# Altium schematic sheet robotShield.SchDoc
size A2; DocumentNumber: 3; SheetNumber: 1; SheetTotal: 1; PageSetup: Record=PageOptions¦CenterHorizontal=True¦CenterVertical=True¦PrintScale=0.73¦XCorrection=1.00¦YCorrection=1.00¦PrintKind=0¦BorderSize=5000000¦LeftOffset=0¦BottomOffset=0¦Orientation=2¦PaperLength=1000¦PaperWidth=1000¦Scale=100¦PaperSource=7¦PrintQuality=-3¦MediaType=1¦DitherType=10¦PrintScaleMode=1¦PaperKind=A3¦PaperIndex=8
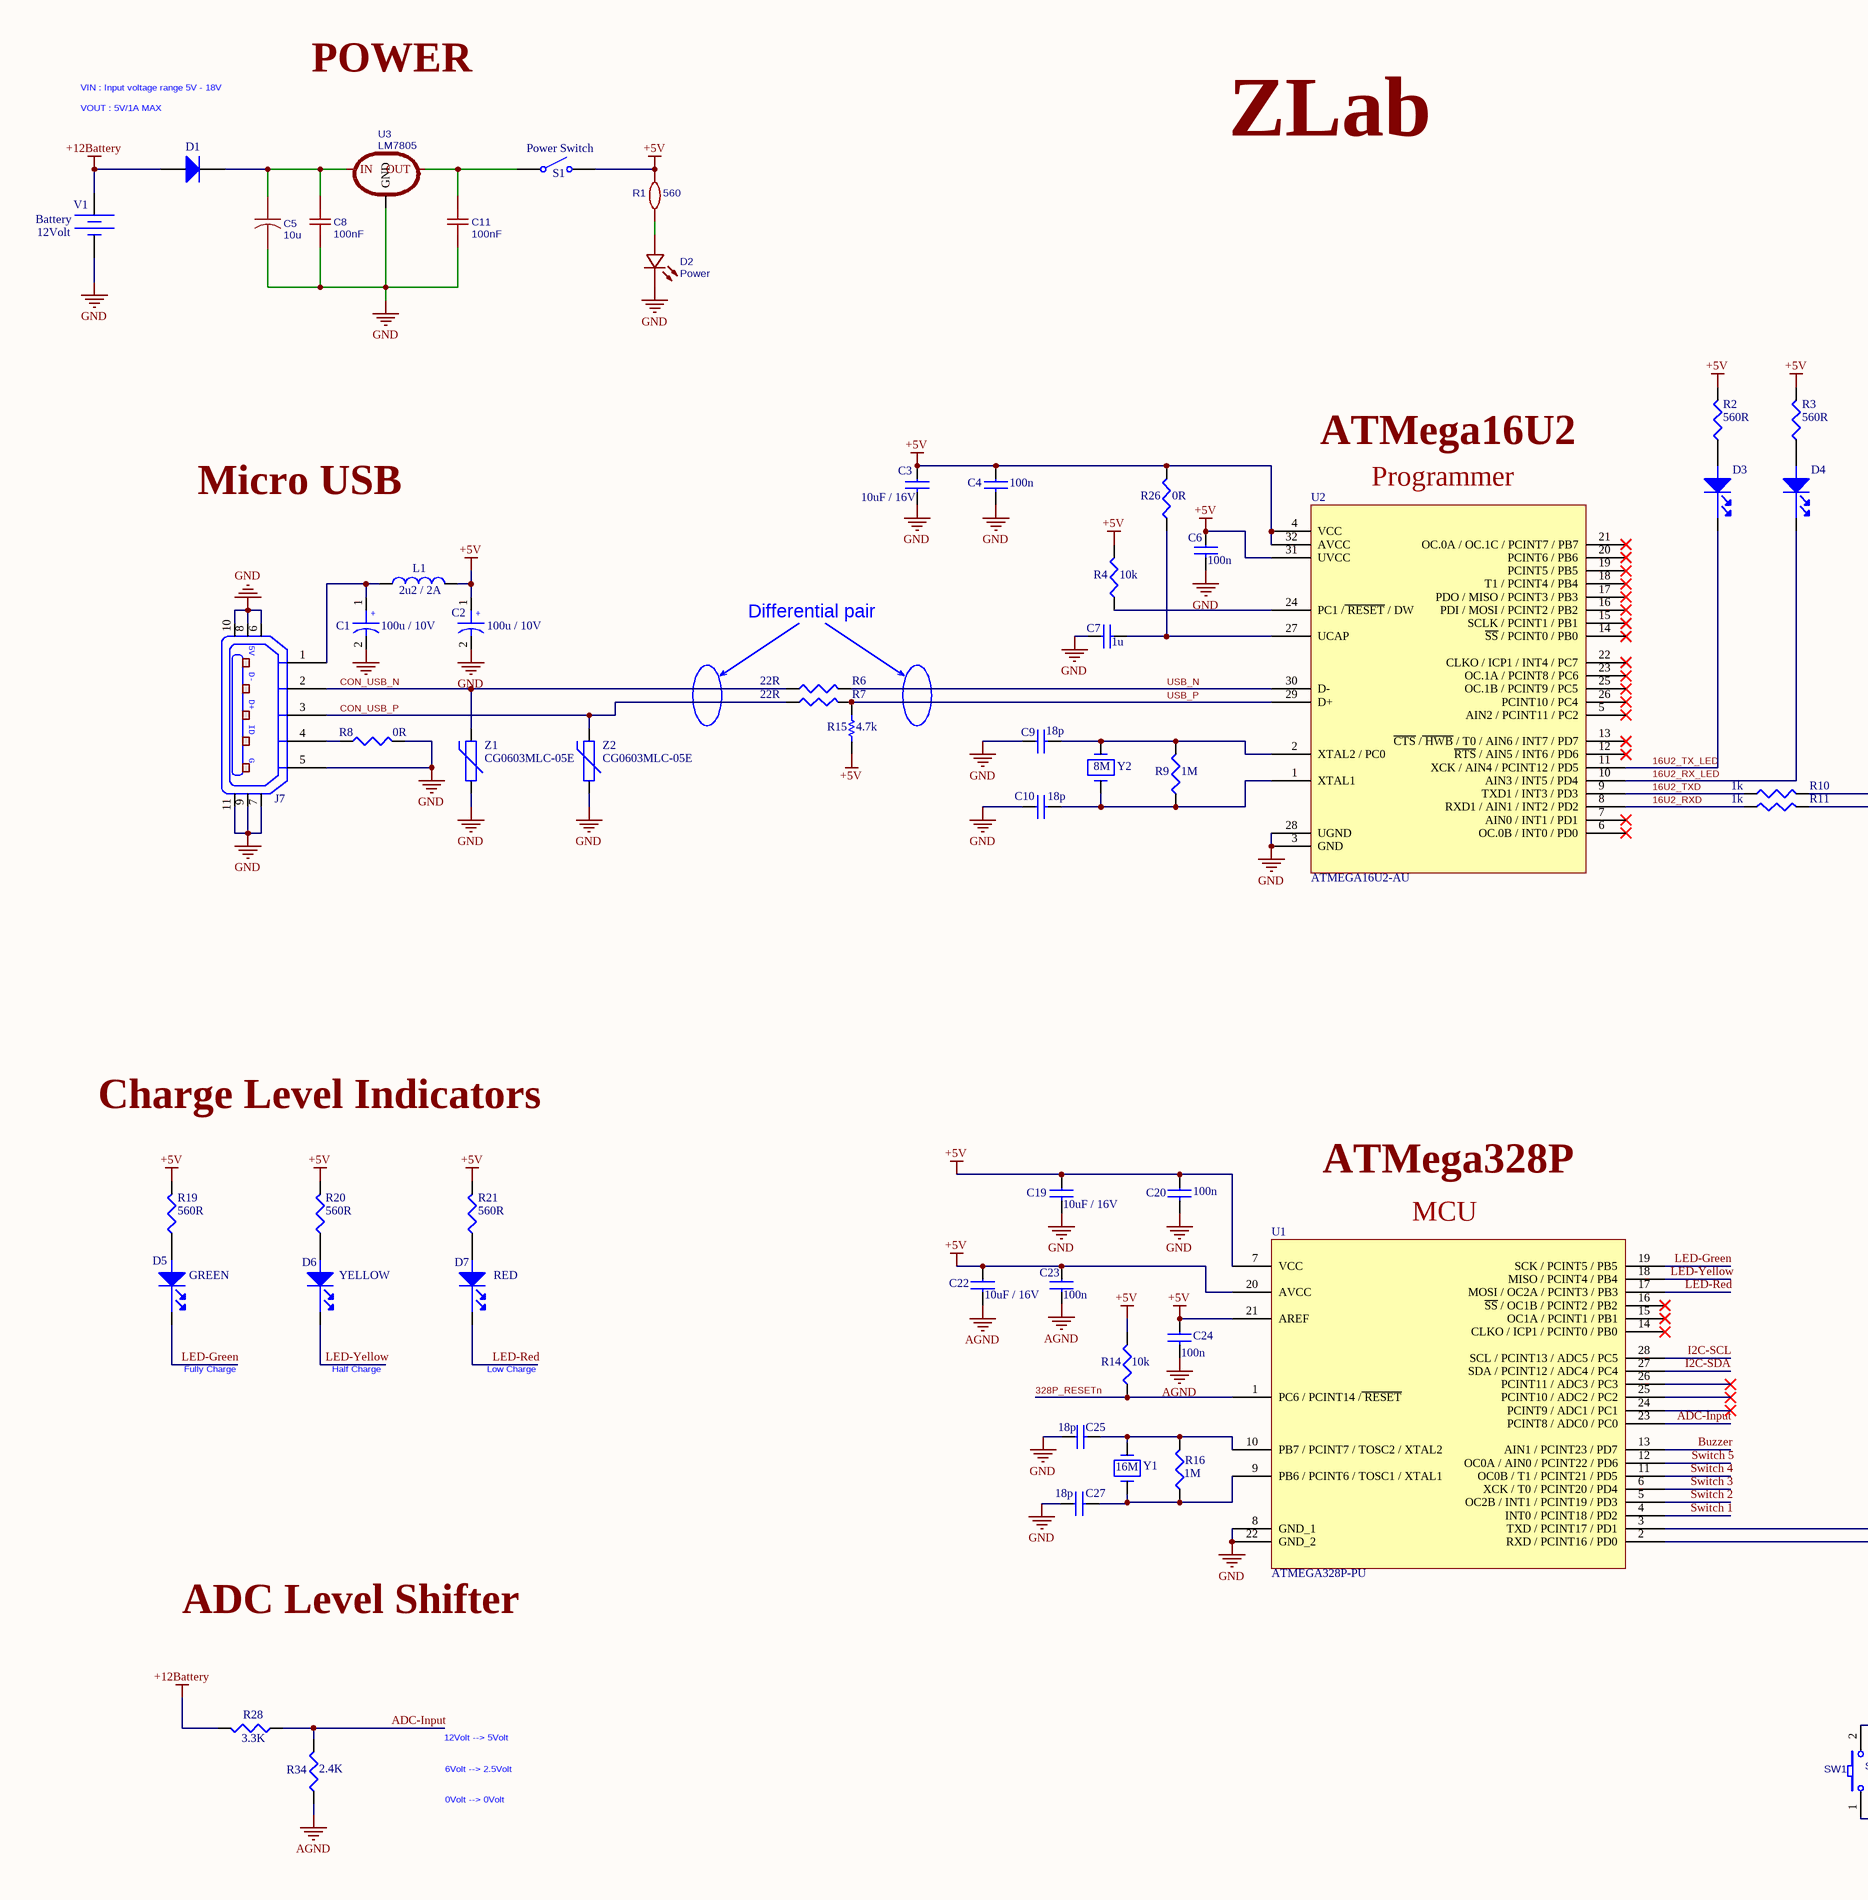
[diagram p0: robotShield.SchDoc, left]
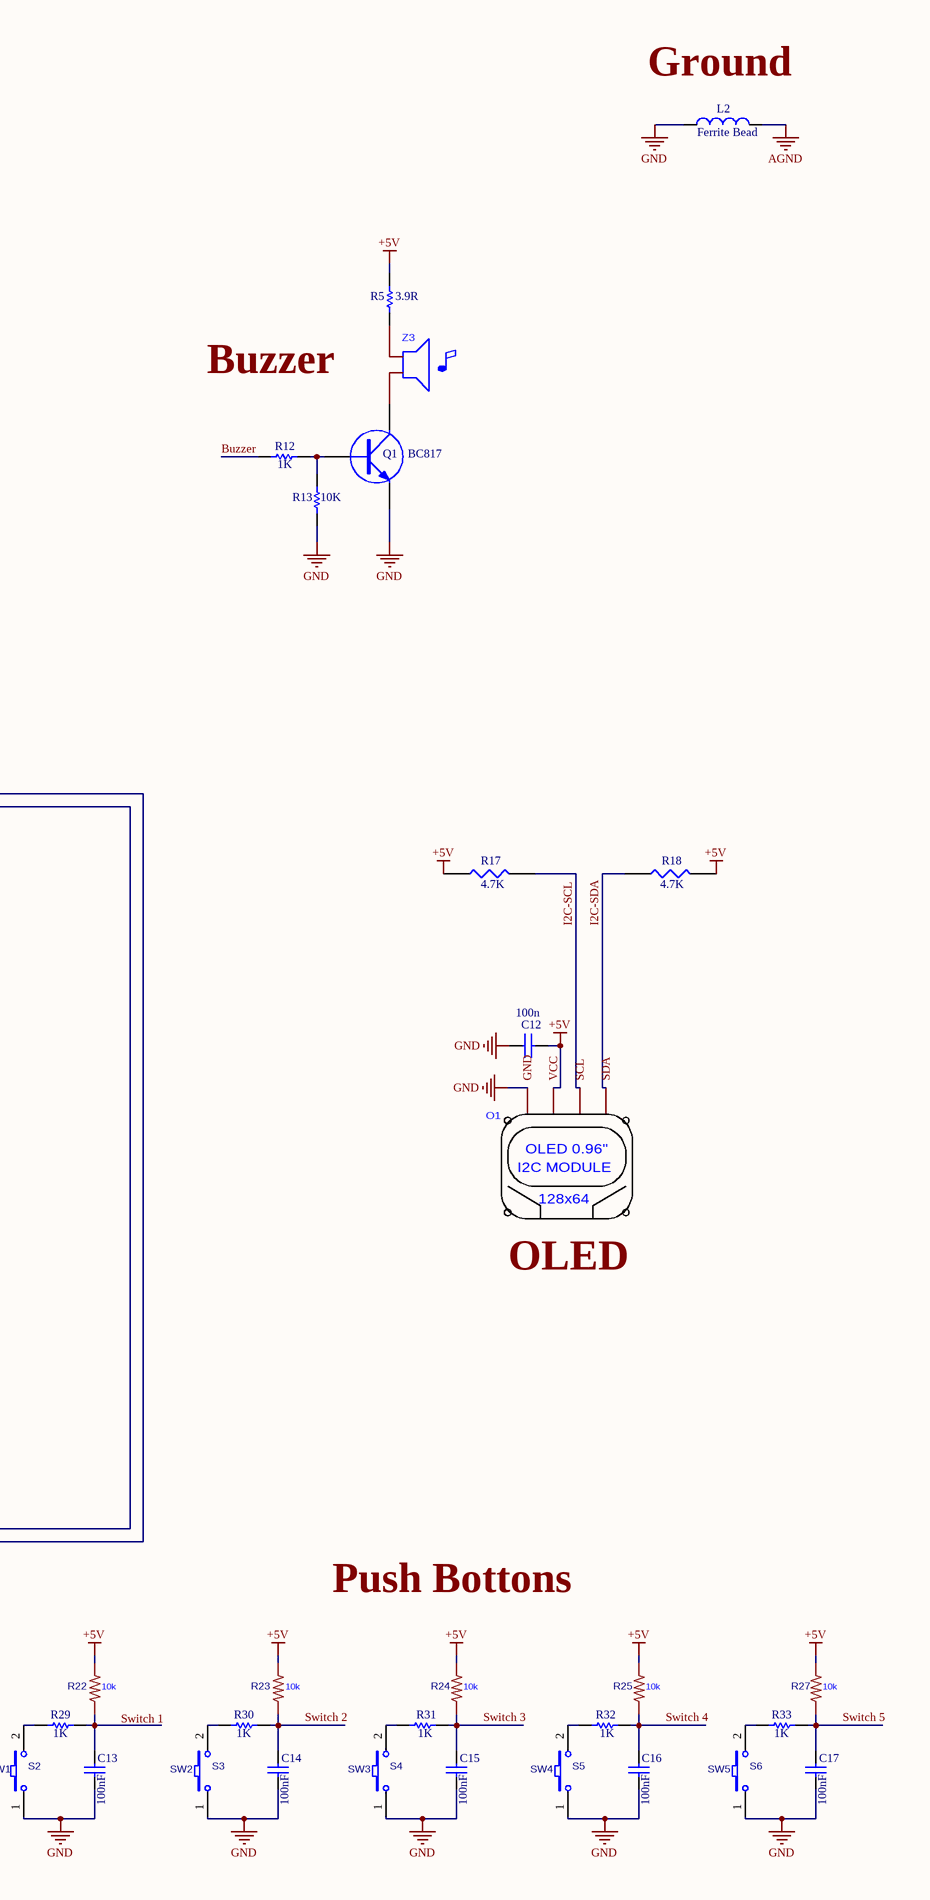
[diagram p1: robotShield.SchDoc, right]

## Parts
C1  100u / 10V  [C_ALU_C_SIZE]
C2  100u / 10V  [C_ALU_C_SIZE]
C3  10uF / 16V  [C_ALU_C_SIZE]
C4  100n  [C0805]
C5  10u  [C_ALU_C_SIZE]
C6  100n  [C0805]
C7  1u  [C0805]
C8  100nF  [R0805]
C9  18p  [C0805]
C10  18p  [C0805]
C11  100nF  [R0805]
C12  100n  [C0805]
C13  value 100nF  [C0805]  (hidden comment: Cap)
C14  value 100nF  [C0805]  (hidden comment: Cap)
C15  value 100nF  [C0805]  (hidden comment: Cap)
C16  value 100nF  [C0805]  (hidden comment: Cap)
C17  value 100nF  [C0805]  (hidden comment: Cap)
C19  10uF / 16V  [C0805]
C20  100n  [C0805]
C22  10uF / 16V  [C0805]
C23  100n  [C0805]
C24  100n  [C0805]
C25  18p  [C0805]
C27  18p  [C0805]
D1  Diode  [SOD323]  (value not drawn)
D2  Power  [LED_0603]
D3  (no value)  [LED_0603]
D4  (no value)  [LED_0603]
D5  GREEN  [LED_0603]
D6  YELLOW  [LED_0603]
D7  RED  [LED_0603]
J7  (no value)  [10118193]
L1  2u2 / 2A  [ABM7_v1_1_BIG]
L2  Ferrite Bead  [C1210_IND]
O1  (no value)  [OLED-TH_OLED0.96-I2C_FP]
Q1  BC817  [DBV_SOT_23_5]
R1  560  [R0805]
R2  560R  [R0603]
R3  560R  [R0603]
R4  10k  [R0805]
R5  value 3.9R  [R0805]  (hidden comment: 1K)
R6  22R  [R0805]
R7  22R  [R0805]
R8  0R  [R0805]
R9  1M  [R0603]
R10  1k  [R0805]
R11  1k  [R0805]
R12  1K  [R0805]
R13  10K  [R0805]
R14  10k  [R0805]
R15  value 4.7k  [R0805]  (hidden comment: Res1)
R16  1M  [R0805]
R17  4.7K  [R0805]
R18  4.7K  [R0805]
R19  560R  [R0805]
R20  560R  [R0805]
R21  560R  [R0805]
R22  0.22OHM-1_4W-1%(0805)  [R0805]  (value not drawn)
R23  0.22OHM-1_4W-1%(0805)  [R0805]  (value not drawn)
R24  0.22OHM-1_4W-1%(0805)  [R0805]  (value not drawn)
R25  0.22OHM-1_4W-1%(0805)  [R0805]  (value not drawn)
R26  0R  [R0805]
R27  0.22OHM-1_4W-1%(0805)  [R0805]  (value not drawn)
R28  3.3K  [R0805]
R29  value 1K  [R0805]
R30  value 1K  [R0805]
R31  value 1K  [R0805]
R32  value 1K  [R0805]
R33  value 1K  [R0805]
R34  2.4K  [R0805]
S1  Power Switch
S2  SW1  [SMD PUSH BUTTON]
S3  SW2  [SMD PUSH BUTTON]
S4  SW3  [SMD PUSH BUTTON]
S5  SW4  [SMD PUSH BUTTON]
S6  SW5  [SMD PUSH BUTTON]
U1  ATMEGA328P-PU  [28_DIP_7.62mm]
U2  ATMEGA16U2-AU  [TQFP32]
U3  LM7805  [L7805]
V1  Battery  DC Magnitude: 12Volt
Y1  16M  [ABM7_v1_1_BIG]
Y2  8M  [Model Name]
Z1  CG0603MLC-05E  [SOD323]
Z2  CG0603MLC-05E  [SOD323]
Z3  (no value)  [BUZZER_3V]

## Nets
+5V: C2.1 C3.1 C4.1 C6.1 C12.2 C19.1 C20.1 C22.1 C23.1 C24.1 L1.2 R1.2 R2.2 R3.2 R4.2 R5.1 R14.2 R15.1 R17.1 R18.2 R19.2 R20.2 R21.2 R22.2 R23.2 R24.2 R25.2 R26.2 R27.2 S1.2 U1.7(VCC) U1.20(AVCC) U1.21(AREF) U2.4(VCC) U2.31(UVCC) U2.32(AVCC)
+12Battery: D1.1(A) R28.2 V1.1
AGND: C22.2 C24.2 L2.2 R34.1
GND: C1.2 C2.2 C3.2 C4.2 C5.2 C6.2 C7.1 C8.1 C9.1 C10.1 C11.1 C12.1 C13.1 C14.1 C15.1 C16.1 C17.1 C19.2 C20.2 C25.1 C27.1 D2.K J7.5(P5) J7.6 J7.7 J7.8 J7.9 J7.10 J7.11 Q1.2 R8.2 R13.2 S2.1 S3.1 S4.1 S5.1 S6.1 U1.8(GND_1) U1.22(GND_2) U2.3(GND) U2.28(UGND) U3.2(GND) V1.2 Z1.1 Z2.1
16U2_RX_LED: D4.1(cathode) U2.10(AIN3_/_INT5_/_PD4)
16U2_RXD: R11.1 U2.8(RXD1_/_AIN1_/_INT2_/_PD2)
16U2_TX_LED: D3.1(cathode) U2.11(XCK_/_AIN4_/_PCINT12_/_PD5)
16U2_TXD: R10.1 U2.9(TXD1_/_INT3_/_PD3)
328P_RESETn: R14.1 U1.1(PC6_/_PCINT14_/~{_RESET})
ADC-Input: R28.1 R34.2 U1.23(PCINT8_/_ADC0_/_PC0)
Buzzer: R12.2 U1.13(AIN1_/_PCINT23_/_PD7)
CON_USB_N: J7.2(P2) R6.1 Z1.2
CON_USB_P: J7.3(P3) R7.1 Z2.2
I2C-SCL: R17.2 U1.28(SCL_/_PCINT13_/_ADC5_/_PC5)
I2C-SDA: R18.1 U1.27(SDA_/_PCINT12_/_ADC4_/_PC4)
LED-Green: D5.1(cathode) U1.19(SCK_/_PCINT5_/_PB5)
LED-Red: D7.1(cathode) U1.17(MOSI_/_OC2A_/_PCINT3_/_PB3)
LED-Yellow: D6.1(cathode) U1.18(MISO_/_PCINT4_/_PB4)
Switch 1: U1.4(INT0_/_PCINT18_/_PD2)
Switch 2: C14.2 R23.1 R30.2 U1.5(OC2B_/_INT1_/_PCINT19_/_PD3)
Switch 3: C15.2 R24.1 R31.2 U1.6(XCK_/_T0_/_PCINT20_/_PD4)
Switch 4: C16.2 R25.1 R32.2 U1.11(OC0B_/_T1_/_PCINT21_/_PD5)
Switch 5: C17.2 R27.1 R33.2 U1.12(OC0A_/_AIN0_/_PCINT22_/_PD6)
USB_N: R6.2 U2.30(D-)
USB_P: R7.2 R15.2 U2.29(D+)
NetC1_1: C1.1 J7.1(P1) L1.1
NetC5_1: C5.1 C8.2 D1.2(K) U3.1(IN)
NetC7_2: C7.2 R26.1 U2.27(UCAP)
NetC9_2: C9.2 R9.2 U2.2(XTAL2_/_PC0) Y2.2
NetC10_2: C10.2 R9.1 U2.1(XTAL1) Y2.1
NetC11_2: C11.2 S1.1 U3.3(OUT)
NetC13_2: C13.2 R22.1 R29.2
NetC25_2: C25.2 R16.2 U1.10(PB7_/_PCINT7_/_TOSC2_/_XTAL2) Y1.2
NetC27_2: C27.2 R16.1 U1.9(PB6_/_PCINT6_/_TOSC1_/_XTAL1) Y1.1
NetD2_A: D2.A R1.1
NetD3_2: D3.2(ANODE) R2.1
NetD4_2: D4.2(ANODE) R3.1
NetD5_2: D5.2(ANODE) R19.1
NetD6_2: D6.2(ANODE) R20.1
NetD7_2: D7.2(ANODE) R21.1
NetJ7_4: J7.4(P4) R8.1
NetQ1_1: Q1.1 R12.1 R13.1
NetQ1_3: Q1.3 Z3.2
NetR4_1: R4.1 U2.24(PC1_/~{_RESET}_/_DW)
NetR5_2: R5.2 Z3.1
NetR10_2: R10.2 U1.2(RXD_/_PCINT16_/_PD0)
NetR11_2: R11.2 U1.3(TXD_/_PCINT17_/_PD1)
NetR29_1: R29.1 S2.2
NetR30_1: R30.1 S3.2
NetR31_1: R31.1 S4.2
NetR32_1: R32.1 S5.2
NetR33_1: R33.1 S6.2

Not connected (* = marked no-connect by the designer): C23 2; L2 1; O1 1(GND) 2(VCC) 3(SCL) 4(SDA); U1 14(CLKO_/_ICP1_/_PCINT0_/_PB0)* 15(OC1A_/_PCINT1_/_PB1)* 16(~{SS}_/_OC1B_/_PCINT2_/_PB2)* 24(PCINT9_/_ADC1_/_PC1)* 25(PCINT10_/_ADC2_/_PC2)* 26(PCINT11_/_ADC3_/_PC3)*; U2 5(AIN2_/_PCINT11_/_PC2)* 6(OC.0B_/_INT0_/_PD0)* 7(AIN0_/_INT1_/_PD1)* 12(~{RTS}_/_AIN5_/_INT6_/_PD6)* 13(~{CTS}_/~{_HWB}_/_T0_/_AIN6_/_INT7_/_PD7)* 14(~{SS}_/_PCINT0_/_PB0)* 15(SCLK_/_PCINT1_/_PB1)* 16(PDI_/_MOSI_/_PCINT2_/_PB2)* 17(PDO_/_MISO_/_PCINT3_/_PB3)* 18(T1_/_PCINT4_/_PB4)* 19(PCINT5_/_PB5)* 20(PCINT6_/_PB6)* 21(OC.0A_/_OC.1C_/_PCINT7_/_PB7)* 22(CLKO_/_ICP1_/_INT4_/_PC7)* 23(OC.1A_/_PCINT8_/_PC6)* 25(OC.1B_/_PCINT9_/_PC5)* 26(PCINT10_/_PC4)*

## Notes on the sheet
- VIN : Input voltage range 5V - 18V
- VOUT : 5V/1A MAX
- POWER
- (near L2) Ground
- ZLab
- Buzzer
- Micro USB
- (near U2) Programmer
- ATMega16U2
- Differential pair
- Charge Level Indicators
- (near U1) MCU
- ATMega328P
- OLED
- Fully Charge
- Half Charge
- Low Charge
- ADC Level Shifter
- Push Bottons
- 12Volt --> 5Volt
- (near R22) 10k
- (near R23) 10k
- (near R24) 10k
- (near R25) 10k
- (near R27) 10k
- 6Volt --> 2.5Volt
- 0Volt --> 0Volt
- Labels drawn without touching a wire or pin: AGND, GND, Switch 1

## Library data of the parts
C1 C2 = EEE-1AA101WR: CAP ALUM 100UF 10V 20% SMD; Manufacturer: Panasonic Electronic Components; Capacitance: 100µF; Lifetime @ Temp.: 1000 Hrs @ 85°C; Ripple Current: 50mA; Surface Mount Land Size: 0.209" L x 0.209" W (5.30mm x 5.30mm); .Creator: MM; .Checked PCB: RF
C3 C19 C22 = C2012X5R1C106M: CAP CER 10UF 16V 20% X5R 0805; Manufacturer: TDK Corporation; Manufacturer Part Number: C2012X5R1C106M/1.25; Capacitance: 10µF; .Checked PCB: used
C4 C6 C12 C20 C23 C24 = C2012X7R1H104K085AA: CAP CER 0.1UF 50V 10% X7R 0805; Manufacturer: TDK Corporation; Capacitance: 0.1µF; .Creator: MM; .Checked PCB: RF
C5 = 10u: nameAlias: Value(F)
C7 = C2012X5R1E105K125AA: CAP CER 1UF 25V 10% X5R 0805; Manufacturer: TDK Corporation; Capacitance: 1µF; .Creator: MM; .Checked PCB: RF
C8 C11 = 0.1u: nameAlias: Value(F)
C9 C10 C25 C27 = C0805C180J5GACTU: CAP CER 18PF 50V 5% NP0 0805; Manufacturer: Kemet; Temperature Coefficient: C0G, NP0; .Creator: MM; .Checked PCB: RF
C13-C17 = Cap: Capacitor
D1 = Diode: Default Diode
D2 = RED: nameAlias: Model
D3 D4 = LO L29K-H2K1-24-Z: LED SMARTLED ORANGE 606NM 0603; Manufacturer: OSRAM Opto Semiconductors Inc; Millicandela Rating: 6.3mcd; Voltage - Forward (Vf) Typ: 1.8V; Current - Test: 2mA; Wavelength - Peak: 610nm; Viewing Angle: 160°; Lens Type: Diffused; Lens Style/Size: Rectangle with Flat Top, 1.3mm x 0.8mm; Luminous Flux @ Current - Test: 25 mlm; .Checked PCB: used
D5-D7 = LO L29K-H2K1-24-Z: Manufacturer: OSRAM Opto Semiconductors Inc; Color: Orange; Millicandela Rating: 6.3mcd; Voltage - Forward (Vf) Typ: 1.8V; Current - Test: 2mA; Wavelength - Dominant: 606nm; Wavelength - Peak: 610nm; Viewing Angle: 160°; Lens Type: Diffused; Lens Style/Size: Rectangle with Flat Top, 1.3mm x 0.8mm; Luminous Flux @ Current - Test: 25 mlm; .Checked PCB: used
J7 = 10118193-0001LF: CONN USB MICRO B RECPT SMT R/A; Manufacturer: FCI; Connector Type: USB - micro B; Number of Contacts: 5; Gender: Receptacle; Specifications: USB 2.0; .Creator: MM; .Checked PCB: RF
L1 = L1210R2R2MDWIT: FIXED IND 2.2UH 2A 80 MOHM SMD; Manufacturer: Kemet; Type: Wirewound; Material - Core: Ferrite; Inductance: 2.2µH; Tolerance: ±20%; Shielding: Unshielded; DC Resistance (DCR): 80 mOhm; Frequency - Self Resonant: 190MHz; Frequency - Test: 100kHz; .Creator: MM; .Checked PCB: RF
L2 = L1210R2R2MDWIT: Manufacturer: Kemet; Type: Wirewound; Inductance: 2.2µH; Tolerance: ±20%; Current Rating: 2A; Shielding: Unshielded; DC Resistance (DCR): 80 mOhm; Frequency - Self Resonant: 190MHz; Frequency - Test: 100kHz; .Creator: MM; .Checked PCB: RF
O1 = LCD 0.96 I2C SSH1306
Q1 = NPN: NPN Transistor
R1 = 10k: nameAlias: Value(Ω)
R2 R3 R19-R21 R28 R34 = RC0805FR-07560RL: RES SMD 560 OHM 1% 1/8W 0805; Manufacturer: Yageo; Resistance (Ohms): 560; Power (Watts): 0.125W, 1/8W; Temperature Coefficient: ±100ppm/°C; .Creator: MM; .Checked PCB: RF
R4 R14 = RC0805FR-0710KL: RES SMD 10K OHM 1% 1/8W 0805; Manufacturer: Yageo; Power (Watts): 0.125W, 1/8W; Temperature Coefficient: ±100ppm/°C; .Creator: MM; .Checked PCB: RF
R5 R12 R13 R15 R29-R33 = Res1: Resistor
R6 R7 = RC0805FR-0722RL: RES SMD 22 OHM 1% 1/8W 0805; Manufacturer: Yageo; Resistance (Ohms): 22; Power (Watts): 0.125W, 1/8W; Temperature Coefficient: ±100ppm/°C; .Creator: MM; .Checked PCB: RF
R8 R26 = RC0805JR-070RL: RES 0.0 OHM 1/8W 0805 SMD; Manufacturer: Yageo; Resistance (Ohms): 0.0; Power (Watts): 0.125W, 1/8W; Tolerance: Jumper; .Checked PCB: RF
R9 R16 = RC0805FR-071ML: RES SMD 1M OHM 1% 1/8W 0805; Manufacturer: Yageo; Power (Watts): 0.125W, 1/8W; Temperature Coefficient: ±100ppm/°C; .Creator: MM; .Checked PCB: RF
R10 R11 = RC0805FR-071KL: RES SMD 1K OHM 1% 1/8W 0805; Manufacturer: Yageo; Power (Watts): 0.125W, 1/8W; Temperature Coefficient: ±100ppm/°C; .Creator: MM; .Checked PCB: RF
R17 R18 = RES1
R22-R25 R27 = 0.22OHM-1_4W-1%(0805): catid: 20; Contributor: SparkFun
S1 = SPST SW: Single-Pole, Single-Throw Switch; closed: 0; Rclosed: 1m; Ropen: 1Meg; SimulationGenericComponent: True
S2-S6 = Button1: catid: 20; sourceId: K60iAuM3l
U1 = ATMEGA328P-PU: IC MCU 8BIT 32KB FLASH 28DIP; Manufacturer: Atmel; Core Processor: AVR; Core Size: 8-Bit; Speed: 20MHz; Connectivity: I²C, SPI, UART/USART; Peripherals: Brown-out Detect/Reset, POR, PWM, WDT; Number of I/O: 23; Program Memory Size: 32KB (16K x 16); EEPROM Size: 1K x 8; RAM Size: 2K x 8; Voltage - Supply (Vcc/Vdd): 1.8 V ~ 5.5 V; Data Converters: A/D 6x10b; Oscillator Type: Internal; .Creator: MM; .Checked PCB: RF
U2 = ATMEGA16U2-AU: IC MCU 8BIT 16KB FLASH 32TQFP; Manufacturer: Atmel; Core Processor: AVR; Core Size: 8-Bit; Speed: 16MHz; Connectivity: SPI, UART/USART, USB; Peripherals: Brown-out Detect/Reset, POR, PWM, WDT; Number of I/O: 22; Program Memory Size: 16KB (8K x 16); EEPROM Size: 512 x 8; Voltage - Supply (Vcc/Vdd): 2.7 V ~ 5.5 V; Oscillator Type: Internal; .Creator: MM; .Checked PCB: RF
U3 = LM7805: catid: 20; nameAlias: Model
V1 = Battery: Constant Voltage Source; SimulationGenericComponent: True
Y1 Y2 = ABM7-16.000MHZ-D2Y-T: Manufacturer: Abracon LLC; Frequency: 16MHz; Frequency Stability: ±30ppm; Frequency Tolerance: ±20ppm; Load Capacitance: 18pF; ESR (Equivalent Series Resistance): 50 Ohm; Operating Mode: Fundamental; .Creator: MM; .Checked PCB: RF
Z1 Z2 = CG0603MLC-05E: VARISTOR 0603; Manufacturer: Bourns Inc.; Number of Circuits: 1; Maximum DC Volts: 5VDC; .Creator: MM; .Checked PCB: RF
Z3 = buzzer_piezo_3v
